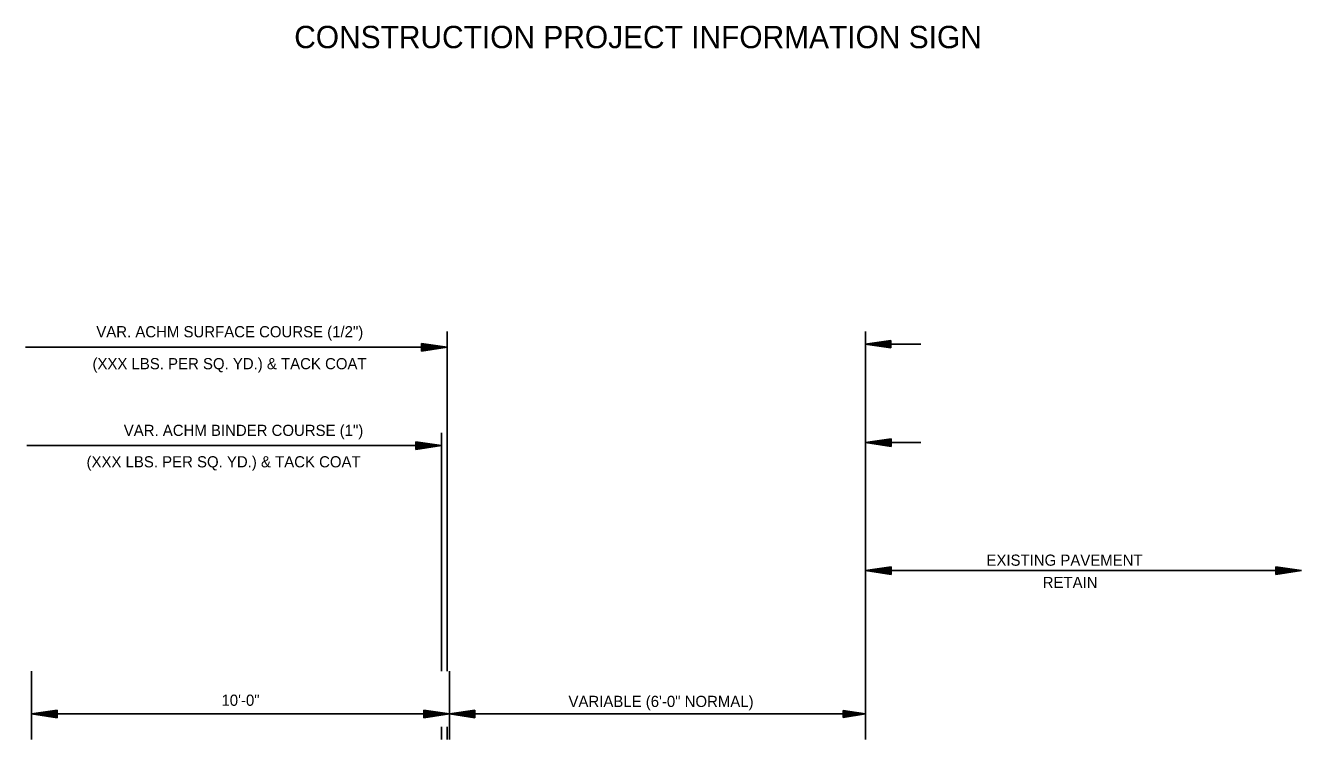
# Model space of a CAD drawing. Extents: x 635488 to 635865, y 290537 to 290973.
# Drawn here: x 635495.4 to 635563.9, y 290896.7 to 290935.1 of the extents above; entities that cross this region are included whole.
import ezdxf

# ---------------------------------------------------------------- set-up
doc = ezdxf.new("R2010")
doc.units = 0
doc.layers.add('Default', color=7, linetype='Continuous')

msp = doc.modelspace()

# ---------------------------------------------------------------- linework, layer by layer
at = {"layer": 'Default'}
for p, q in [((635516.685, 290918.021), (635518.055, 290917.817)), ((635516.685, 290918.021), (635516.685, 290917.611)), ((635518.055, 290918.668), (635518.055, 290900.414)), ((635541.87, 290918.186), (635540.502, 290917.982)), ((635540.519, 290918.668), (635540.519, 290896.749)), ((635541.87, 290918.153), (635540.729, 290917.982)), ((635541.87, 290918.118), (635540.965, 290917.982)), ((635541.87, 290918.085), (635541.194, 290917.982)), ((635541.87, 290918.046), (635541.426, 290917.982)), ((635541.87, 290918.015), (635541.653, 290917.982)), ((635541.87, 290917.776), (635541.87, 290918.186)), ((635495.427, 290917.817), (635518.055, 290917.817)), ((635516.685, 290917.988), (635517.828, 290917.817)), ((635516.685, 290917.953), (635517.591, 290917.817)), ((635516.685, 290917.92), (635517.363, 290917.817)), ((635516.685, 290917.881), (635517.131, 290917.817)), ((635516.685, 290917.85), (635516.904, 290917.817)), ((635516.685, 290917.611), (635518.055, 290917.817)), ((635516.685, 290917.749), (635517.131, 290917.817)), ((635516.685, 290917.68), (635517.591, 290917.817)), ((635516.685, 290917.646), (635517.828, 290917.817)), ((635516.685, 290917.716), (635517.363, 290917.817)), ((635516.685, 290917.784), (635516.904, 290917.817)), ((635541.87, 290917.776), (635540.502, 290917.982)), ((635540.502, 290917.982), (635543.487, 290917.982)), ((635541.87, 290917.811), (635540.729, 290917.982)), ((635541.87, 290917.845), (635540.965, 290917.982)), ((635541.87, 290917.881), (635541.194, 290917.982)), ((635541.87, 290917.914), (635541.426, 290917.982)), ((635541.87, 290917.949), (635541.653, 290917.982)), ((635517.748, 290913.214), (635517.748, 290900.414)), ((635495.497, 290912.53), (635517.748, 290912.53)), ((635516.378, 290912.734), (635517.748, 290912.53)), ((635516.378, 290912.734), (635516.378, 290912.324)), ((635516.378, 290912.701), (635517.517, 290912.53)), ((635516.378, 290912.665), (635517.284, 290912.53)), ((635516.378, 290912.633), (635517.056, 290912.53)), ((635516.378, 290912.595), (635516.824, 290912.53)), ((635516.378, 290912.562), (635516.595, 290912.53)), ((635516.378, 290912.324), (635517.748, 290912.53)), ((635516.378, 290912.461), (635516.824, 290912.53)), ((635516.378, 290912.393), (635517.284, 290912.53)), ((635516.378, 290912.358), (635517.517, 290912.53)), ((635516.378, 290912.427), (635517.056, 290912.53)), ((635516.378, 290912.499), (635516.595, 290912.53)), ((635541.887, 290912.899), (635540.519, 290912.695)), ((635540.519, 290912.695), (635543.487, 290912.695)), ((635541.887, 290912.489), (635540.519, 290912.695)), ((635541.887, 290912.866), (635540.745, 290912.695)), ((635541.887, 290912.523), (635540.745, 290912.695)), ((635541.887, 290912.83), (635540.98, 290912.695)), ((635541.887, 290912.558), (635540.98, 290912.695)), ((635541.887, 290912.798), (635541.207, 290912.695)), ((635541.887, 290912.592), (635541.207, 290912.695)), ((635541.887, 290912.76), (635541.44, 290912.695)), ((635541.887, 290912.626), (635541.44, 290912.695)), ((635541.887, 290912.727), (635541.669, 290912.695)), ((635541.887, 290912.664), (635541.669, 290912.695)), ((635541.887, 290912.489), (635541.887, 290912.899)), ((635541.889, 290906.021), (635540.519, 290905.817)), ((635540.519, 290905.817), (635563.917, 290905.817)), ((635541.889, 290905.611), (635540.519, 290905.817)), ((635541.889, 290905.988), (635540.746, 290905.817)), ((635541.889, 290905.645), (635540.746, 290905.817)), ((635541.889, 290905.952), (635540.983, 290905.817)), ((635541.889, 290905.679), (635540.983, 290905.817)), ((635541.889, 290905.919), (635541.212, 290905.817)), ((635541.889, 290905.715), (635541.212, 290905.817)), ((635541.889, 290905.882), (635541.443, 290905.817)), ((635541.889, 290905.748), (635541.443, 290905.817)), ((635541.889, 290905.849), (635541.671, 290905.817)), ((635541.889, 290905.784), (635541.671, 290905.817)), ((635541.889, 290905.611), (635541.889, 290906.021)), ((635562.549, 290906.022), (635563.917, 290905.817)), ((635562.549, 290905.611), (635562.549, 290906.022)), ((635562.549, 290905.986), (635563.69, 290905.817)), ((635562.549, 290905.952), (635563.456, 290905.817)), ((635562.549, 290905.919), (635563.229, 290905.817)), ((635562.549, 290905.882), (635562.996, 290905.817)), ((635562.549, 290905.848), (635562.766, 290905.817)), ((635562.549, 290905.611), (635563.917, 290905.817)), ((635562.549, 290905.751), (635562.996, 290905.817)), ((635562.549, 290905.679), (635563.456, 290905.817)), ((635562.549, 290905.645), (635563.69, 290905.817)), ((635562.549, 290905.714), (635563.229, 290905.817)), ((635562.549, 290905.782), (635562.766, 290905.817)), ((635495.751, 290900.414), (635495.751, 290896.749)), ((635518.183, 290900.414), (635518.183, 290896.749)), ((635497.119, 290898.323), (635495.751, 290898.119)), ((635497.119, 290898.29), (635495.98, 290898.119)), ((635497.119, 290898.254), (635496.217, 290898.119)), ((635497.119, 290898.221), (635496.446, 290898.119)), ((635497.119, 290898.184), (635496.677, 290898.119)), ((635497.119, 290898.151), (635496.906, 290898.119)), ((635497.119, 290898.323), (635497.119, 290897.913)), ((635516.813, 290898.323), (635518.183, 290898.119)), ((635516.813, 290897.913), (635516.813, 290898.323)), ((635516.813, 290898.29), (635517.955, 290898.119)), ((635516.813, 290898.254), (635517.72, 290898.119)), ((635516.813, 290898.221), (635517.491, 290898.119)), ((635516.813, 290898.184), (635517.26, 290898.119)), ((635516.813, 290898.151), (635517.033, 290898.119)), ((635519.551, 290898.323), (635518.183, 290898.119)), ((635519.551, 290898.29), (635518.412, 290898.119)), ((635519.551, 290898.254), (635518.646, 290898.119)), ((635519.551, 290898.221), (635518.873, 290898.119)), ((635519.551, 290898.184), (635519.109, 290898.119)), ((635519.551, 290898.151), (635519.336, 290898.119)), ((635519.551, 290898.323), (635519.551, 290897.913)), ((635539.319, 290898.299), (635540.519, 290898.119)), ((635539.319, 290897.939), (635539.319, 290898.299)), ((635539.319, 290898.269), (635540.319, 290898.119)), ((635539.319, 290898.238), (635540.112, 290898.119)), ((635539.319, 290898.208), (635539.912, 290898.119)), ((635539.319, 290898.178), (635539.709, 290898.119)), ((635539.319, 290898.147), (635539.509, 290898.119)), ((635518.183, 290898.119), (635495.751, 290898.119)), ((635497.119, 290897.913), (635495.751, 290898.119)), ((635497.119, 290897.947), (635495.98, 290898.119)), ((635497.119, 290897.981), (635496.217, 290898.119)), ((635497.119, 290898.017), (635496.446, 290898.119)), ((635497.119, 290898.05), (635496.677, 290898.119)), ((635497.119, 290898.086), (635496.906, 290898.119)), ((635516.813, 290897.913), (635518.183, 290898.119)), ((635516.813, 290898.05), (635517.26, 290898.119)), ((635516.813, 290897.981), (635517.72, 290898.119)), ((635516.813, 290897.947), (635517.955, 290898.119)), ((635516.813, 290898.017), (635517.491, 290898.119)), ((635516.813, 290898.086), (635517.033, 290898.119)), ((635540.519, 290898.119), (635518.183, 290898.119)), ((635519.551, 290897.913), (635518.183, 290898.119)), ((635519.551, 290897.947), (635518.412, 290898.119)), ((635519.551, 290897.981), (635518.646, 290898.119)), ((635519.551, 290898.017), (635518.873, 290898.119)), ((635519.551, 290898.05), (635519.109, 290898.119)), ((635519.551, 290898.086), (635519.336, 290898.119)), ((635539.319, 290897.939), (635540.519, 290898.119)), ((635539.319, 290898.061), (635539.709, 290898.119)), ((635539.319, 290898), (635540.112, 290898.119)), ((635539.319, 290897.969), (635540.319, 290898.119)), ((635539.319, 290898.03), (635539.912, 290898.119)), ((635539.319, 290898.091), (635539.509, 290898.119)), ((635517.748, 290897.435), (635517.748, 290896.749)), ((635518.055, 290897.435), (635518.055, 290896.749)), ((635518.183, 290897.435), (635518.183, 290896.749))]:
    msp.add_line(p, q, dxfattribs=at)

# ---------------------------------------------------------------- texts
for s, height, p in [('CONSTRUCTION PROJECT INFORMATION SIGN', 1.2, (635509.85, 290933.877)), ('VAR. ACHM SURFACE COURSE (1/2")', 0.6, (635499.227, 290918.349)), ('(XXX LBS. PER SQ. YD.) & TACK COAT', 0.6, (635499.021, 290916.633)), ('VAR. ACHM BINDER COURSE (1")', 0.6, (635500.7, 290913.052)), ('(XXX LBS. PER SQ. YD.) & TACK COAT', 0.6, (635498.702, 290911.364)), ('EXISTING PAVEMENT', 0.6, (635547.008, 290906.08)), ('RETAIN', 0.6, (635550.027, 290904.882)), ('10\'-0"', 0.6, (635505.945, 290898.558)), ('VARIABLE (6\'-0" NORMAL)', 0.6, (635524.572, 290898.495))]:
    msp.add_text(s, height=height, dxfattribs=at).set_placement(p)

doc.saveas('drawing.dxf')
